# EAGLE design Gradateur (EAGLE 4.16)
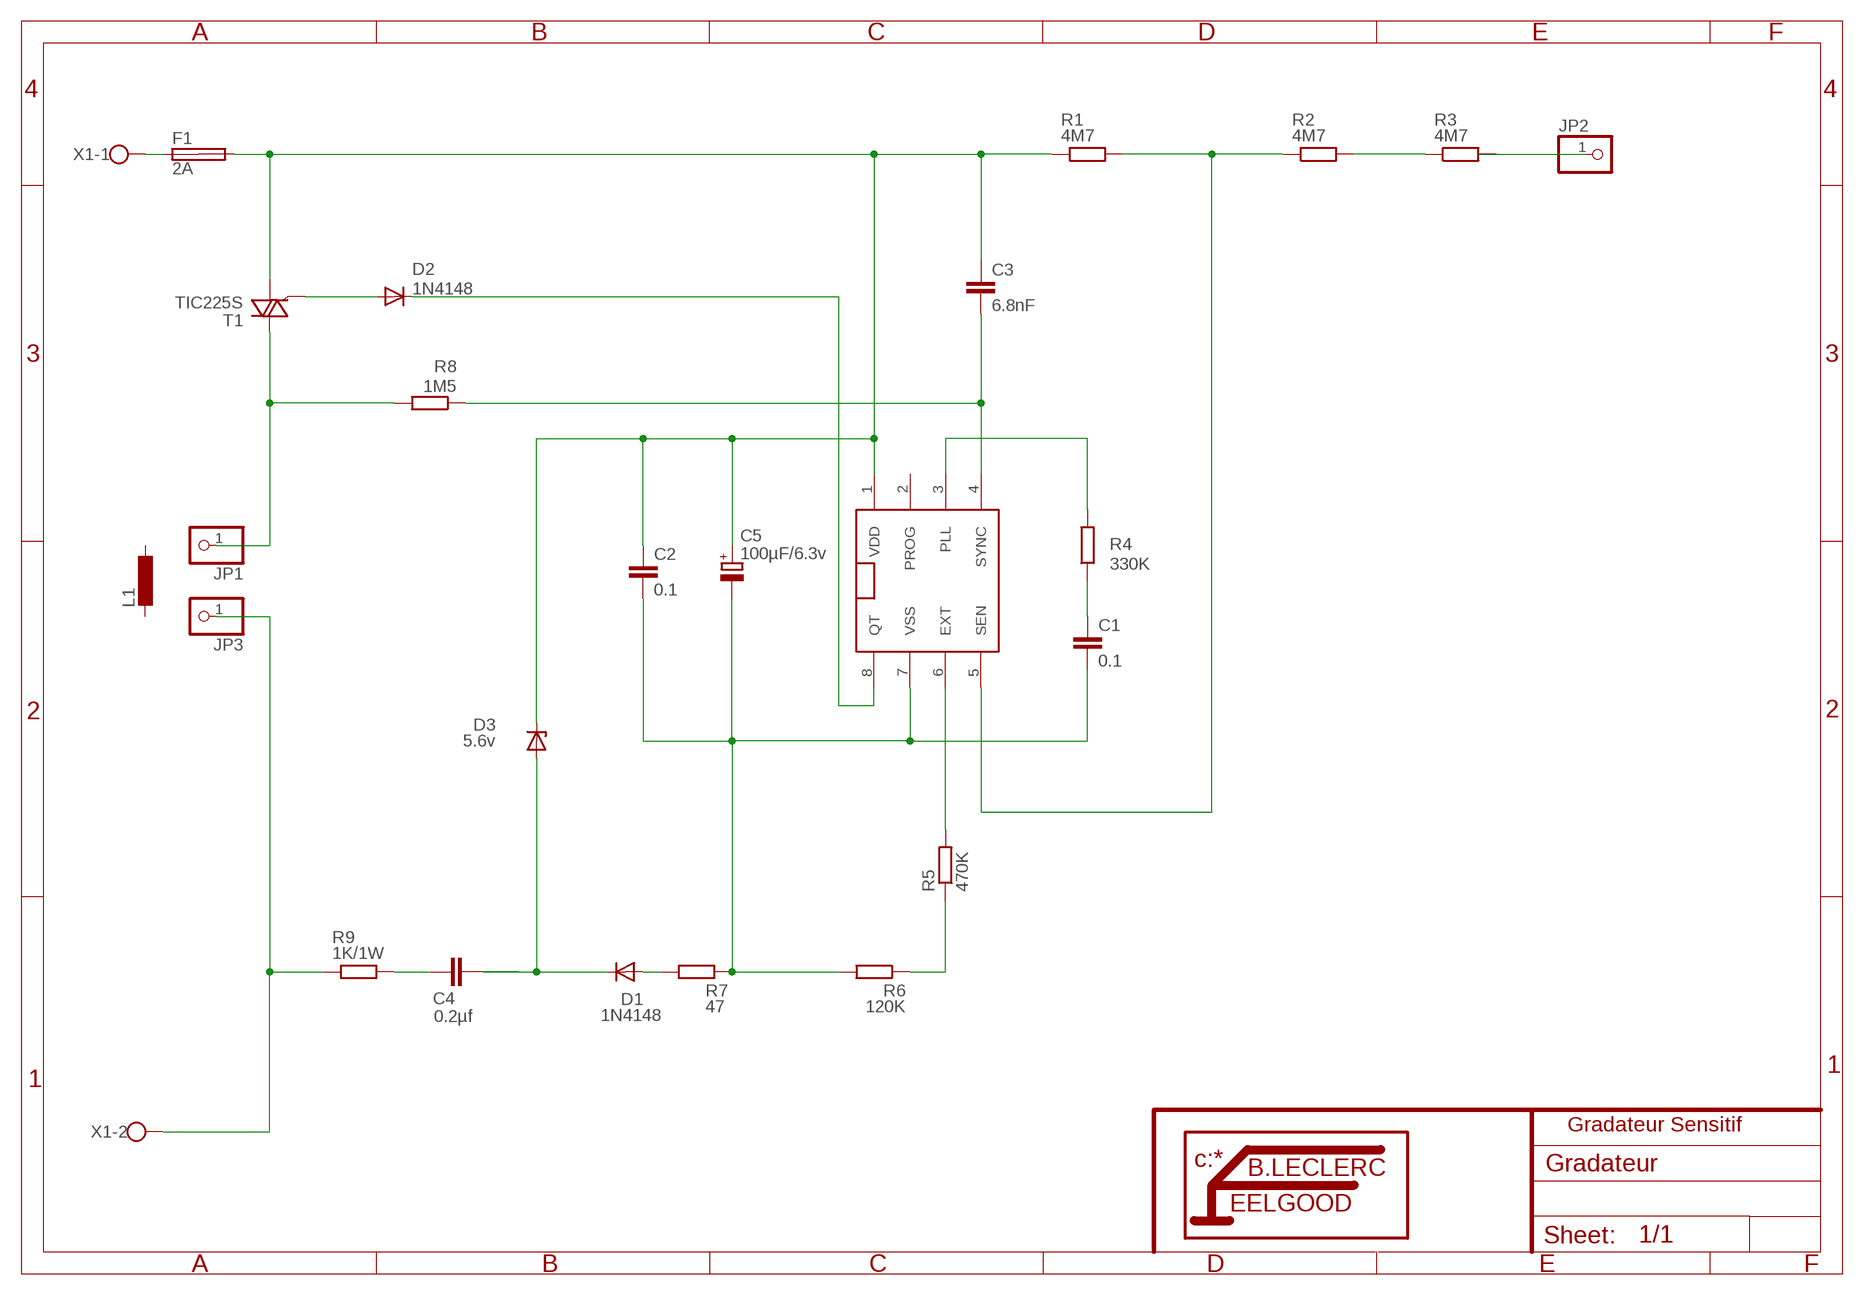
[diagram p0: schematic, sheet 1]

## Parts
C1  0.1  C-EU102-043X133  [C102-043X133]
C2  0.1  C-EU102-043X133  [C102-043X133]
C3  6.8nF  C-EU075-032X103  [C075-032X103]
C4  0.2µf  C-EU102-054X133  [C102-054X133]
C5  100µF/6.3v  CPOL-EUE5-6  [E5-6]
D1  1N4148  [DO35-10]
D2  1N4148  [DO35-10]
D3  5.6v  ZENER-DIODEF126-10  [F126Z10]
F1  2A  SHK20L  [SHK20L]
JP1  PINHD-1X1  [1X01]
JP2  PINHD-1X1  [1X01]
JP3  PINHD-1X1  [1X01]
L1  L-EU0204/7  [0204/7]
R1  4M7  R-EU_0207/10  [0207/10]
R2  4M7  R-EU_0207/10  [0207/10]
R3  4M7  R-EU_0207/10  [0207/10]
R4  330K  R-EU_0207/10  [0207/10]
R5  470K  R-EU_0207/10  [0207/10]
R6  120K  R-EU_0207/10  [0207/10]
R7  47  R-EU_0207/10  [0207/10]
R8  1M5  R-EU_0207/10  [0207/10]
R9  1K/1W  R-EU_0411/12  [0411/12]
T1  TIC225S  [TO220DS]
U1  SLB0587  [SLB0587]
X1  W237-102  [W237-102]

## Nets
N$1: F1.1A X1.1
N$2: C2.1 C3.1 C5.+ D3.C F1.2A R1.1 T1.A1 U1.1(VDD)
N$3: JP1.1 R8.2 T1.A2
N$4: C4.1 R9.2
N$5: JP3.1 R9.1 X1.2
N$6: C4.2 D1.C D3.A
N$7: D1.A R7.2
N$8: C1.2 C2.2 C5.- R6.2 R7.1 U1.7(VSS)
N$9: R5.1 R6.1
N$11: R5.2 U1.6(EXT)
N$14: C1.1 R4.1
N$15: R4.2 U1.3(PLL)
N$16: R2.2 R3.1
N$17: R1.2 R2.1 U1.5(SEN)
N$19: C3.2 R8.1 U1.4(SYNC)
N$21: D2.A T1.G
N$22: D2.C U1.8(QT)
N$23: JP2.1 R3.2
Unconnected: F1.1B F1.2B L1.1 L1.2 U1.2(PROG)

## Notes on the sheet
- Gradateur Sensitif

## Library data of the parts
C1-C4 = rcl:C-EU: CAPACITOR, European symbol
C5 = rcl:CPOL-EU: POLARIZED CAPACITOR, European symbol
D1 D2 = diode:1N4148: DIODE
D3 = diode:ZENER-DIODE: Z-Diode
F1 = fuse:SHK20L: FUSE HOLDER 5 x 20 mm, SH contact, SHH1 Schukat, E1073 Buerklin
JP1-JP3 = pinhead:PINHD-1X1: PIN HEADER
L1 = rcl:L-EU: INDUCTOR, European symbol
R1-R9 = rcl:R-EU_: RESISTOR, European symbol
T1 = triac:TIC225S: TRIAC
U1 = Siemens:SLB0587
X1 = con-wago-500:W237-102: WAGO SCREW CLAMP

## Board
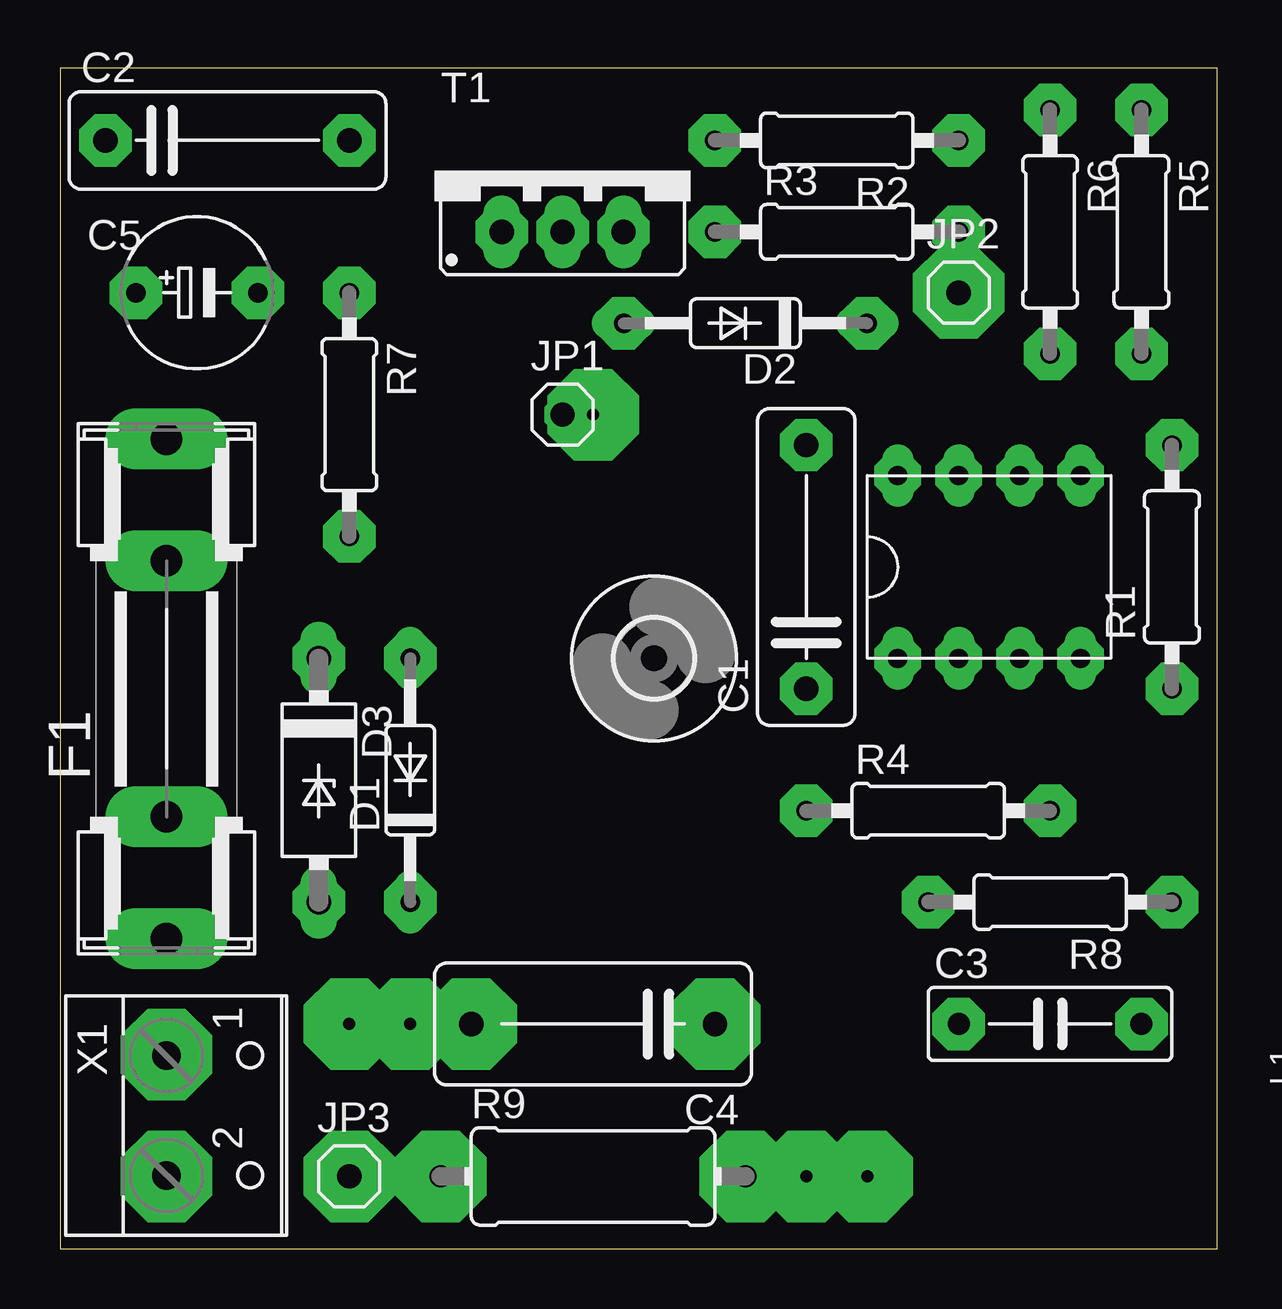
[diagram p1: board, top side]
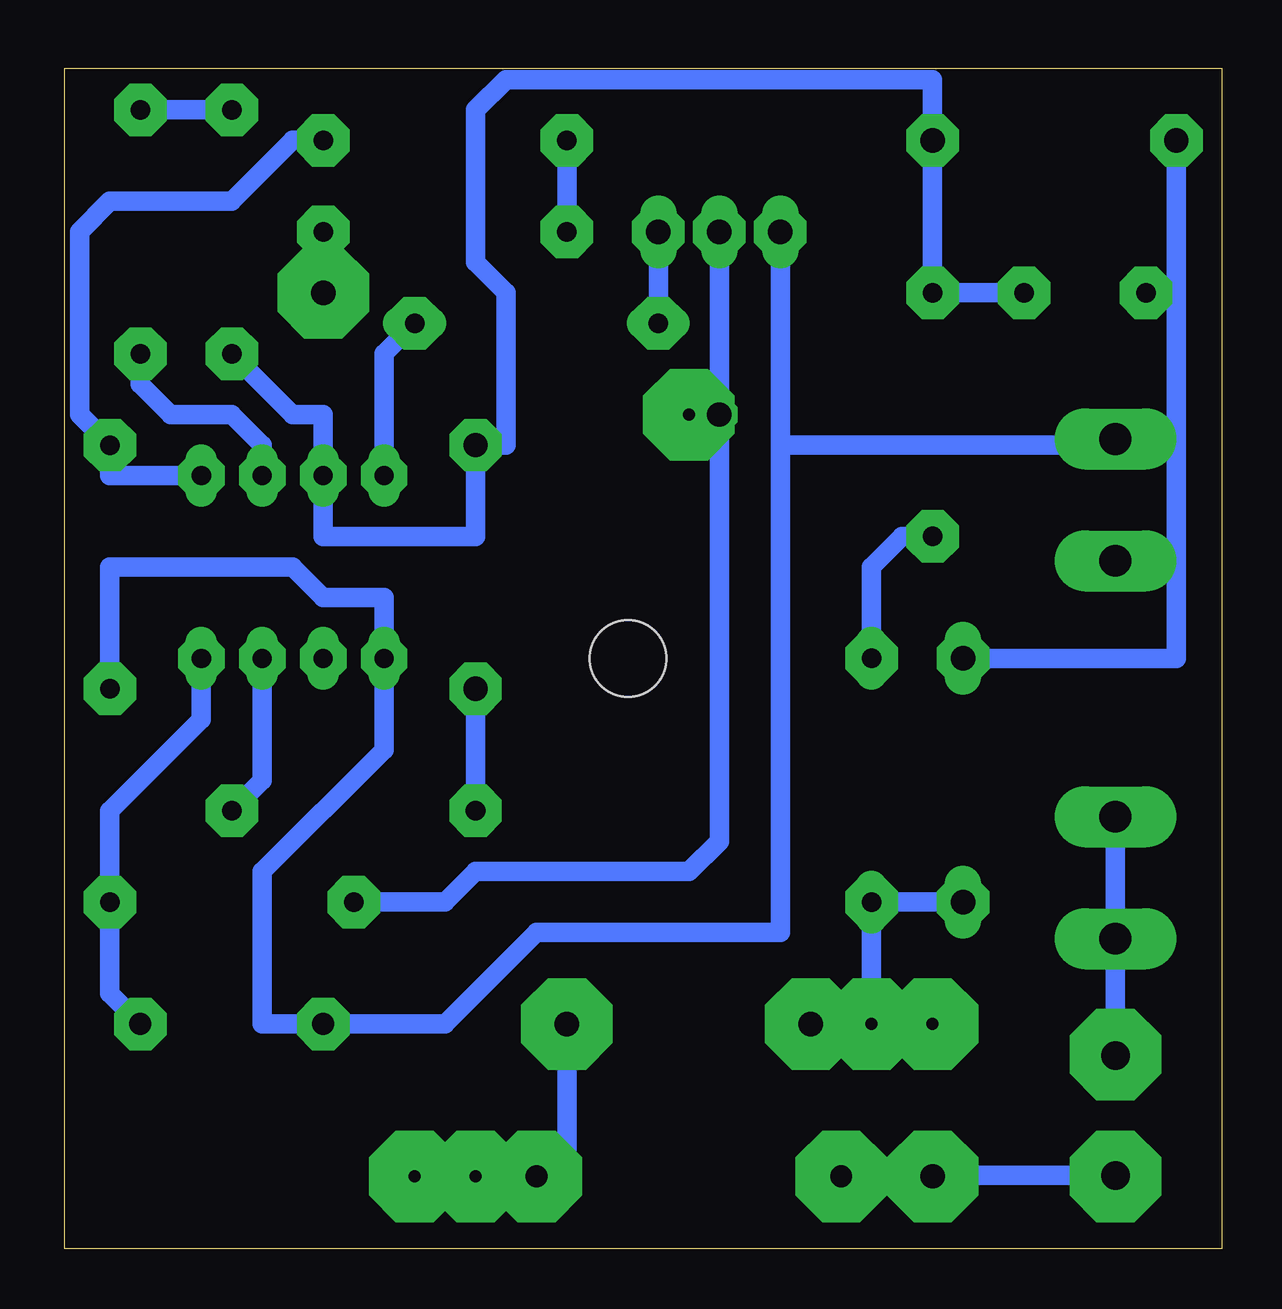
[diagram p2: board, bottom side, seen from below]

Size 48.24 x 49.2 mm. Coordinates in mm from the lower left corner, seen from the top.
Outline: 0,0 48.24,0 48.24,49.2 0,49.2 0,0
Copper layers (1*16): Top 0.035mm / dielectric 1.5mm / Bottom 0.035mm
Design rules "default": minimum track width 10mil, minimum drill 24mil, track to track 8mil, track to pad 8mil, pad to pad 8mil, via to via 8mil, smd to smd 8mil, copper to edge 40mil, drill to drill 8mil, minimum pad ring 10mil, minimum via ring 8mil, stop-mask expansion 4mil, vias tented up to drill 0mil, thermal gap 10mil

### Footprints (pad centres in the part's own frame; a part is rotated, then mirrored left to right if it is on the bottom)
C102-043X133 = drill 1.016 octagon: 1 -5.08,0; 2 5.08,0
C075-032X103 = drill 0.914 octagon: 1 -3.81,0; 2 3.81,0
C102-054X133 = drill 1.016 octagon: 1 -5.08,0; 2 5.08,0
E5-6 = drill 0.813 pad 1.905 round: + -2.54,0 | drill 0.813 pad 1.905 octagon: - 2.54,0
DO35-10 = drill 0.813 long: A 5.08,0; C -5.08,0
F126Z10 = drill 1.016 long: A 5.08,0; C -5.08,0
SHK20L = drill 1.321 pad 2.54 long: 1A -10.414,0; 1B -5.334,0; 2A 10.414,0; 2B 5.334,0
1X01 = drill 1.016 octagon: 1 0,0
0204/7 = drill 0.813 octagon: 1 -3.81,0; 2 3.81,0
0207/10 = drill 0.813 octagon: 1 -5.08,0; 2 5.08,0
0411/12 = drill 0.914 octagon: 1 -6.35,0; 2 6.35,0
TO220DS = drill 1.016 long: A1 -2.54,-2.54; A2 0,-2.54; G 2.54,-2.54
SLB0587 = drill 0.8 long: 1 -3.81,-3.81; 2 -1.27,-3.81; 3 1.27,-3.81; 4 3.81,-3.81; 5 3.81,3.81; 6 1.27,3.81; 7 -1.27,3.81; 8 -3.81,3.81
3,2 = hole 3.2: 0,0
W237-102 = drill 1.194 long: 1 -2.5,-1.27; 2 2.5,-1.27

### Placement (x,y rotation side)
C1  31.11,28.41 90 top
C2  6.98,46.19 0 top
C3  41.27,9.36 0 top
C4  22.22,9.36 180 top
C5  5.71,39.84 0 top
D1  14.6,19.52 90 top
D2  28.57,38.57 180 top
D3  10.79,19.52 270 top
F1  4.44,23.33 90 top
JP1  20.95,34.76 0 top
JP2  37.46,39.84 0 top
JP3  12.06,3.01 0 top
L1  not placed on the board
R1  46.35,28.41 90 top
R2  32.38,46.19 180 top
R3  32.38,42.38 0 top
R4  36.19,18.25 0 top
R5  45.08,42.38 270 top
R6  41.27,42.38 270 top
R7  12.06,34.76 270 top
R8  41.27,14.44 180 top
R9  22.22,3.01 0 top
T1  20.95,44.92 0 top
U1  38.73,28.41 0 top
U$2  [3,2]  24.76,24.6 0 top
X1  5.71,5.55 270 top

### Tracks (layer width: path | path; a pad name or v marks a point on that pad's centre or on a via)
N$1
  Bottom 0.813: X1.1 F1.1A 4.44,18.25
N$2
  Bottom 0.813: 1.9,39.84 C2.1 | 1.9,39.84 C5.+ | 1.9,33.49 1.9,39.84 | 1.9,33.49 4.44,33.49 | 1.9,33.49 1.9,33.74 F1.2A 4.44,33.49 | 1.9,33.49 1.9,24.6 D3.C | 18.41,33.49 T1.A1 | 4.44,33.49 18.41,33.49 | 18.41,33.49 18.41,13.17 28.57,13.17 32.38,9.36 C3.1 40,9.36 40,15.71 34.92,20.79 U1.1 34.92,27.14 37.46,27.14 38.73,28.41 46.35,28.41 R1.1
N$3
  Bottom 0.813: T1.A2 JP1.1 20.95,16.98 22.22,15.71 31.11,15.71 32.38,14.44 R8.2
N$4
  Bottom 0.813: R9.2 27.3,3.01 C4.1
N$5
  Bottom 0.813: X1.2 12.06,3.05 JP3.1 R9.1
N$6
  Bottom 0.813: C4.2 14.6,9.36 D1.C D3.A
N$7
  Bottom 0.813: R7.2 13.33,29.68 14.6,28.41 D1.A
N$8
  Bottom 0.813: C5.- R7.1 C2.2 12.06,48.73 29.84,48.73 31.11,47.46 31.11,41.11 29.84,39.84 29.84,33.49 C1.2 31.11,29.68 37.46,29.68 U1.7 37.46,34.76 38.73,34.76 R6.2
N$9
  Bottom 0.813: R6.1 R5.1
N$10  (via drill 0.5 pad 3.81)
  other vias: 28.57,3.01
N$11
  Bottom 0.813: U1.6 40,33.49 41.27,34.76 43.81,34.76 45.08,36.03 R5.2
N$12  (via drill 0.5 pad 3.81)
  other vias: 15.87,3.01
N$13  (via drill 0.5 pad 3.81)
  other vias: 4.44,8.09
N$14
  Bottom 0.813: R4.1 C1.1
N$15
  Bottom 0.813: U1.3 40,19.52 R4.2
N$16
  Bottom 0.813: R3.1 R2.2
N$17
  Bottom 0.813: U1.5 46.35,32.22 R1.2 47.62,34.76 47.62,42.38 46.35,43.65 41.27,43.65 38.73,46.19 R2.1
N$18  (via drill 0.5 pad 3.81)
  other vias: 4.44,3.01
N$19
  Bottom 0.813: C3.2 46.35,10.63 R8.1 46.35,18.25 42.54,22.06 U1.4
N$20  (via drill 0.5 pad 3.81)
  other vias: 31.11,3.01
N$21
  Bottom 0.813: D2.A T1.G
N$22
  Bottom 0.813: U1.8 34.92,37.3 D2.C
N$23
  Bottom 0.813: JP2.1 R3.2
N$24  (via drill 0.5 pad 3.81)
  other vias: 12.06,3.01
N$25  (via drill 0.5 pad 3.81)
  other vias: 33.65,3.01
N$26  (via drill 0.5 pad 3.81)
  other vias: 27.3,9.36
N$27  (via drill 0.5 pad 3.81)
  other vias: 14.6,9.36
N$28  (via drill 0.5 pad 3.81)
  other vias: 17.14,9.36
N$29  (via drill 0.5 pad 3.81)
  other vias: 12.06,9.36
N$30  (via drill 0.5 pad 3.81)
  other vias: 22.22,34.76
N$31  (via drill 0.5 pad 3.81)
  other vias: 37.46,39.84
N$32  (via drill 0.5 pad 2.18)
  other vias: 12.06,39.84
N$33  (via drill 0.5 pad 2.18)
  other vias: 12.06,29.68
N$34  (via drill 0.5 pad 2.18)
  other vias: 10.79,24.6
N$35  (via drill 0.5 pad 2.18)
  other vias: 14.6,24.6
N$36  (via drill 0.5 pad 2.18)
  other vias: 10.79,14.44
N$37  (via drill 0.5 pad 2.18)
  other vias: 14.6,14.44
N$38  (via drill 0.5 pad 2.18)
  other vias: 27.3,46.19
N$39  (via drill 0.5 pad 2.18)
  other vias: 37.46,46.19
N$40  (via drill 0.5 pad 2.18)
  other vias: 37.46,42.38
N$41  (via drill 0.5 pad 2.18)
  other vias: 27.3,42.38
N$42  (via drill 0.5 pad 2.18)
  other vias: 41.27,47.46
N$43  (via drill 0.5 pad 2.18)
  other vias: 41.27,37.3
N$44  (via drill 0.5 pad 2.18)
  other vias: 45.08,37.3
N$45  (via drill 0.5 pad 2.18)
  other vias: 45.08,47.46
N$46  (via drill 0.5 pad 2.18)
  other vias: 46.35,33.49
N$47  (via drill 0.5 pad 2.18)
  other vias: 46.35,23.33
N$48  (via drill 0.5 pad 2.18)
  other vias: 8.25,39.84
N$49  (via drill 0.5 pad 2.18)
  other vias: 3.17,39.84
N$50  (via drill 0.5 pad 2.18)
  other vias: 12.06,46.19
N$51  (via drill 0.5 pad 2.18)
  other vias: 1.9,46.19
N$52  (via drill 0.5 pad 2.18)
  other vias: 41.27,18.25
N$53  (via drill 0.5 pad 2.18)
  other vias: 31.11,18.25
N$54  (via drill 0.5 pad 2.18)
  other vias: 36.19,14.44
N$55  (via drill 0.5 pad 2.18)
  other vias: 46.35,14.44
N$56  (via drill 0.5 pad 2.18)
  other vias: 37.46,9.36
N$57  (via drill 0.5 pad 2.18)
  other vias: 45.08,9.36
N$58  (via drill 0.5 pad 2.18)
  other vias: 31.11,33.49
N$59  (via drill 0.5 pad 2.18)
  other vias: 31.11,23.33
N$60  (via drill 0.5 pad 2.18)
  other vias: 18.41,42.38
N$61  (via drill 0.5 pad 2.18)
  other vias: 20.95,42.38
N$62  (via drill 0.5 pad 2.18)
  other vias: 23.49,42.38
N$63  (via drill 0.5 pad 2.18)
  other vias: 23.49,38.57
N$64  (via drill 0.5 pad 2.18)
  other vias: 33.65,38.57
N$65  (via drill 0.5 pad 1.93)
  other vias: 34.92,32.22
N$66  (via drill 0.5 pad 1.93)
  other vias: 37.46,32.22
N$67  (via drill 0.5 pad 1.93)
  other vias: 42.54,32.22
N$68  (via drill 0.5 pad 1.93)
  other vias: 34.92,24.6
N$69  (via drill 0.5 pad 1.93)
  other vias: 37.46,24.6
N$70  (via drill 0.5 pad 1.93)
  other vias: 42.54,24.6
N$71  (via drill 0.5 pad 1.93)
  other vias: 40,24.6
N$72  (via drill 0.5 pad 1.93)
  other vias: 40,32.22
